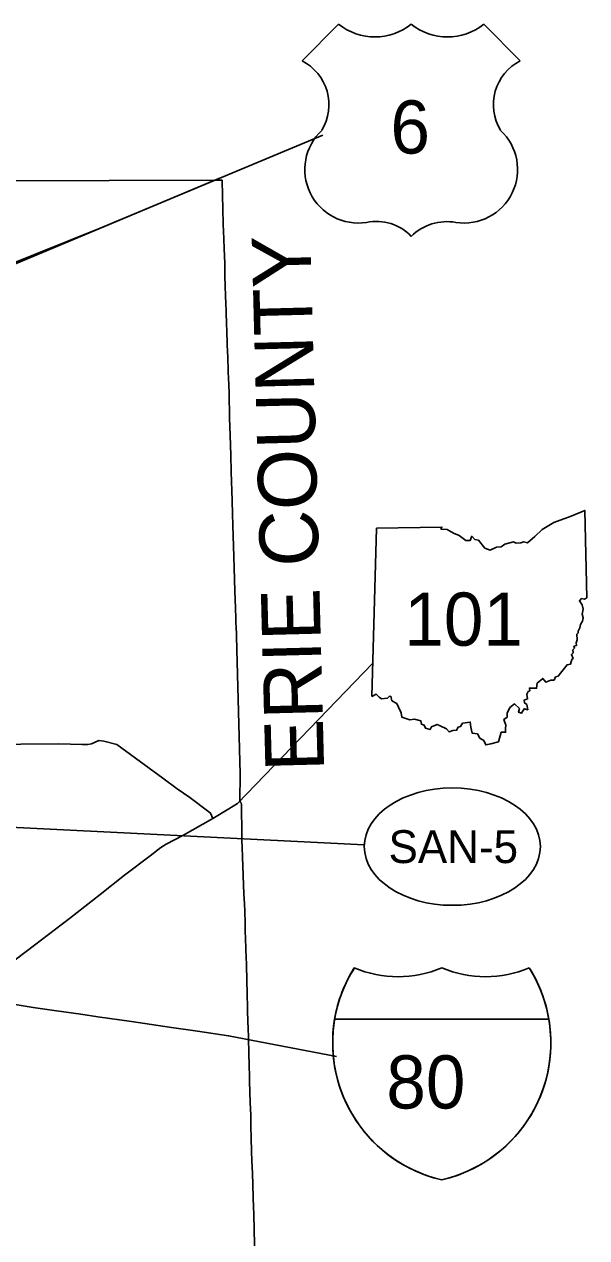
# Model space of a CAD drawing. Extents: x 0 to 798, y 0 to 440.
# Drawn here: x 540.4 to 588.3, y 195.7 to 299.1 of the extents above; entities that cross this region are included whole.
import ezdxf

# ---------------------------------------------------------------- set-up
doc = ezdxf.new("R2010")
doc.units = 0
for name, color, linetype in [('GM_X_Adjacent_County_Text', 7, 'Continuous'), ('GM_X_County', 7, 'Continuous'), ('GM_X_Interstate_Route', 7, 'Continuous'), ('GM_X_State_Route', 7, 'Continuous'), ('GM_X_US_Route', 7, 'Continuous'), ('PV_P_Text', 7, 'Continuous'), ('SH_Data', 7, 'Continuous'), ('SH_Text', 7, 'Continuous')]:
    doc.layers.add(name, color=color, linetype=linetype)

msp = doc.modelspace()

# ---------------------------------------------------------------- linework, layer by layer
at = {"layer": 'GM_X_County'}
msp.add_lwpolyline([(538.64, 285.73), (556.57, 285.78), (557.22, 285.79), (557.25, 284.49), (557.28, 283.34), (557.32, 282.03), (557.35, 280.8), (557.39, 279.94), (557.44, 278.71), (557.46, 277.81), (557.49, 276.58), (557.5, 276.13), (557.54, 275.1), (557.55, 274.86), (557.56, 274.65), (557.57, 274.17), (557.58, 273.91), (557.6, 273.34), (557.61, 273.13), (557.63, 272.64), (557.65, 272.15), (557.66, 271.82), (557.67, 271.13), (557.69, 270.77), (557.71, 270.33), (557.72, 269.89), (557.74, 269.4), (557.76, 268.95), (557.79, 268.34), (557.81, 267.68), (557.82, 267.02), (557.84, 266.16), (557.85, 265.69), (557.85, 265.67), (557.85, 265.53), (557.9, 264.03), (557.95, 262.35), (557.99, 260.95), (558.07, 258.49), (558.09, 257.35), (558.1, 257.18), (558.1, 257.1), (558.12, 256.65), (558.13, 256.36), (558.21, 253.74), (558.24, 252.76), (558.3, 250.79), (558.35, 249.36), (558.38, 248.45), (558.39, 248.08), (558.42, 247.68), (558.42, 247.55), (558.43, 247.27), (558.45, 246.57), (558.45, 246.41), (558.46, 246.37), (558.46, 246.25), (558.46, 246.15), (558.46, 246.03), (558.47, 245.95), (558.47, 245.8), (558.74, 235.2), (558.72, 232.88), (558.78, 232.8), (558.83, 232.73), (558.85, 232.69), (558.86, 232.65), (558.87, 232.64), (558.87, 232.62), (558.88, 232.58), (558.88, 232.33), (558.88, 232.29), (558.88, 232.17), (558.88, 232.09), (558.88, 231.68), (558.89, 230.9), (558.9, 229.46), (558.91, 229.01), (558.95, 228.07), (558.98, 227.41), (559.01, 226.51), (559.08, 224.99), (559.12, 224.14), (559.14, 223.51), (559.18, 222.49), (559.19, 221.87), (559.24, 220.4), (559.27, 219.43), (559.28, 219.13), (559.32, 217.4), (559.34, 216.71), (559.38, 215.06), (559.41, 214.12), (559.43, 213.51), (559.44, 213.27), (559.45, 213.02), (559.46, 212.75), (559.46, 212.58), (559.49, 211.5), (559.53, 210.27), (559.54, 209.53), (559.56, 209), (559.61, 207.2), (559.65, 206.14), (559.66, 205.68), (559.67, 205.11), (559.68, 204.27), (559.68, 204.24), (559.72, 203.01), (559.75, 202.28), (559.79, 201.17), (559.83, 200.23), (559.87, 199.12), (559.9, 198.3), (559.91, 197.73), (559.96, 196.33), (560, 194.03)], dxfattribs=at)
at = {"layer": 'GM_X_Interstate_Route'}
msp.add_lwpolyline([(535.41, 216.44), (535.96, 216.3), (536.34, 216.19), (538.05, 215.82), (541.14, 215.31), (543.1, 215.03), (545.19, 214.73), (546.63, 214.51), (549.5, 214.1), (552.9, 213.6), (555.12, 213.28), (557.77, 212.9), (566.97, 211.14)], dxfattribs=at)
at = {"layer": 'GM_X_State_Route'}
for points in [[(556.43, 231.42), (557.78, 232.23), (558.53, 232.68), (570.04, 244.63)], [(527.85, 237.12), (528.3, 237.17), (530.97, 237.53), (531.94, 237.65), (536.64, 237.68), (540.09, 237.73), (543.32, 237.76), (545.31, 237.72), (545.78, 237.71), (546.1, 237.77), (546.71, 238.04), (547.14, 237.99), (548.24, 237.71), (552.16, 234.85), (553.38, 233.93), (554.47, 233.19), (556.09, 231.97), (556.24, 231.87), (556.43, 231.42)], [(535.41, 216.44), (536.35, 217.09), (538.15, 218.33), (539.71, 219.45), (541.25, 220.63), (544.23, 222.9), (546.83, 224.93), (548.89, 226.57), (551.09, 228.23), (552.01, 228.93), (552.45, 229.22), (553.86, 229.97), (556.43, 231.42)]]:
    msp.add_lwpolyline(points, dxfattribs=at)
at = {"layer": 'GM_X_US_Route'}
msp.add_lwpolyline([(516.74, 268.96), (516.74, 268.97), (520.28, 270.51), (523.66, 272), (525.17, 272.65), (527.51, 273.65), (530.16, 274.76), (533.37, 276.17), (536.78, 277.61), (538.43, 278.33), (546.84, 281.71), (565.78, 289.63)], dxfattribs=at)
at = {"layer": 'PV_P_Text'}
for p, q in [((567.14, 299.07), (564.03, 295.96)), ((567.14, 299.07), (564.03, 295.96)), ((582.61, 295.96), (579.5, 299.07)), ((582.61, 295.96), (579.5, 299.07)), ((569.96, 241.79), (570.36, 256.15)), ((569.96, 241.79), (570.36, 256.15)), ((566.8, 214.31), (585.04, 214.31)), ((585.04, 214.31), (566.8, 214.31)), ((585.04, 214.31), (566.8, 214.31))]:
    msp.add_line(p, q, dxfattribs=at)
for points in [[(570.36, 256.15), (575.94, 256.24), (575.85, 256.07), (576.38, 256.03), (576.93, 255.73), (577.41, 255.53), (577.98, 255.08), (578.33, 255.08), (578.48, 255.46), (578.74, 255.17), (579.06, 255.12), (579.6, 254.43), (580.05, 254.28), (580.58, 254.52), (580.99, 254.55), (581.28, 254.79), (582.04, 254.99), (582.26, 254.87), (582.66, 254.89), (582.87, 254.98), (583.22, 254.9), (583.84, 255.42), (584.48, 256.04), (585.46, 256.62), (586.93, 257.17), (588.1, 257.66), (588.27, 250.21)], [(570.36, 256.15), (575.94, 256.24), (575.85, 256.07), (576.38, 256.03), (576.93, 255.73), (577.41, 255.53), (577.98, 255.08), (578.33, 255.08), (578.48, 255.46), (578.74, 255.17), (579.06, 255.12), (579.6, 254.43), (580.05, 254.28), (580.58, 254.52), (580.99, 254.55), (581.28, 254.79), (582.04, 254.99), (582.26, 254.87), (582.66, 254.89), (582.87, 254.98), (583.22, 254.9), (583.84, 255.42), (584.48, 256.04), (585.46, 256.62), (586.93, 257.17), (588.1, 257.66), (588.27, 250.21)], [(588.27, 250.21), (588.09, 250.1), (587.83, 250.15), (587.65, 249.94), (587.87, 249.6), (587.97, 249.23), (587.88, 248.82), (587.97, 248.49), (587.91, 248.21), (587.74, 247.93), (587.68, 247.66), (587.54, 247.38), (587.55, 247.22), (587.42, 247.1), (587.44, 246.63), (587.37, 246.37), (587.4, 246.15), (587.18, 246.09), (587.23, 245.91), (587.09, 245.77), (587.12, 245.52), (586.96, 245.37), (587.11, 245.05), (586.99, 244.95), (586.89, 244.57), (586.6, 244.5), (586.04, 243.8), (585.84, 243.54), (585.61, 243.47), (585.49, 243.2), (585.21, 243.2), (584.79, 243.01), (584.52, 243.34), (584.05, 242.95), (583.99, 242.5), (583.39, 242.52), (583.42, 242.29), (583.28, 242.22), (583.16, 242), (583.23, 241.59), (582.95, 241.49), (582.98, 241.26), (583.16, 241.11), (583.24, 240.67), (582.95, 240.76), (582.7, 240.38), (582.45, 240.47), (582.53, 240.79), (582.11, 241.17), (581.71, 240.86), (581.5, 240.37), (581.49, 240.04), (581.2, 239.84), (581.39, 239.37), (581.35, 239.05), (581.36, 238.75), (580.98, 238.76), (580.76, 237.93)], [(588.27, 250.21), (588.09, 250.1), (587.83, 250.15), (587.65, 249.94), (587.87, 249.6), (587.97, 249.23), (587.88, 248.82), (587.97, 248.49), (587.91, 248.21), (587.74, 247.93), (587.68, 247.66), (587.54, 247.38), (587.55, 247.22), (587.42, 247.1), (587.44, 246.63), (587.37, 246.37), (587.4, 246.15), (587.18, 246.09), (587.23, 245.91), (587.09, 245.77), (587.12, 245.52), (586.96, 245.37), (587.11, 245.05), (586.99, 244.95), (586.89, 244.57), (586.6, 244.5), (586.04, 243.8), (585.84, 243.54), (585.61, 243.47), (585.49, 243.2), (585.21, 243.2), (584.79, 243.01), (584.52, 243.34), (584.05, 242.95), (583.99, 242.5), (583.39, 242.52), (583.42, 242.29), (583.28, 242.22), (583.16, 242), (583.23, 241.59), (582.95, 241.49), (582.98, 241.26), (583.16, 241.11), (583.24, 240.67), (582.95, 240.76), (582.7, 240.38), (582.45, 240.47), (582.53, 240.79), (582.11, 241.17), (581.71, 240.86), (581.5, 240.37), (581.49, 240.04), (581.2, 239.84), (581.39, 239.37), (581.35, 239.05), (581.36, 238.75), (580.98, 238.76), (580.76, 237.93)], [(580.76, 237.93), (580.11, 237.78), (579.66, 237.68), (579.5, 238.06), (579.17, 238.25), (578.96, 238.63), (578.5, 238.68), (578.39, 239.2), (578.34, 239.62), (577.7, 239.52), (577.53, 239.26), (577.31, 239.19), (577.18, 238.93), (576.87, 238.91), (576.54, 238.79), (576.32, 239.04), (575.79, 239.3), (575.54, 239.43), (575.04, 239.22), (574.93, 238.98), (574.53, 239.09), (574.43, 239.36), (574.19, 239.44), (574.13, 239.73), (573.61, 239.88), (573.21, 239.82), (572.51, 240.05), (572.47, 240.42), (572.23, 240.88), (572.1, 241.2), (571.66, 241.44), (571.57, 241.82), (571.43, 241.81), (571.3, 241.66), (570.8, 241.59), (570.6, 241.74), (570.33, 242.01), (569.96, 241.79)], [(580.76, 237.93), (580.11, 237.78), (579.66, 237.68), (579.5, 238.06), (579.17, 238.25), (578.96, 238.63), (578.5, 238.68), (578.39, 239.2), (578.34, 239.62), (577.7, 239.52), (577.53, 239.26), (577.31, 239.19), (577.18, 238.93), (576.87, 238.91), (576.54, 238.79), (576.32, 239.04), (575.79, 239.3), (575.54, 239.43), (575.04, 239.22), (574.93, 238.98), (574.53, 239.09), (574.43, 239.36), (574.19, 239.44), (574.13, 239.73), (573.61, 239.88), (573.21, 239.82), (572.51, 240.05), (572.47, 240.42), (572.23, 240.88), (572.1, 241.2), (571.66, 241.44), (571.57, 241.82), (571.43, 241.81), (571.3, 241.66), (570.8, 241.59), (570.6, 241.74), (570.33, 242.01), (569.96, 241.79)]]:
    msp.add_lwpolyline(points, dxfattribs=at)
for centre, radius, start, end in [((570.23, 303), 5, 231.813, 308.187), ((570.23, 303), 5, 231.813, 308.187), ((576.41, 303), 5, 231.813, 308.187), ((576.41, 303), 5, 231.813, 308.187), ((562.08, 292.21), 4.23, 329.1175, 62.6108), ((562.08, 292.21), 4.23, 329.1175, 62.6108), ((584.55, 292.21), 4.23, 117.3892, 210.8825), ((584.55, 292.21), 4.23, 117.3892, 210.8825), ((568.82, 286.7), 4.56, 133.0046, 278.7282), ((568.82, 286.7), 4.56, 133.0046, 278.7282), ((577.82, 286.7), 4.56, 261.2718, 46.9954), ((577.82, 286.7), 4.56, 261.2718, 46.9954), ((570.36, 278.2), 4.08, 43.4177, 101.8742), ((570.36, 278.2), 4.08, 43.4177, 101.8742), ((576.37, 277.93), 4.33, 79.9613, 134.7468), ((576.37, 277.93), 4.33, 79.9613, 134.7468), ((578.62, 212.3), 11.99, 147.8216, 256.9941), ((577.87, 212.51), 11.22, 146.654, 170.759), ((572.2, 227.5), 9.57, 247.0848, 292.9105), ((572.2, 227.5), 9.57, 247.0848, 292.9105), ((573.22, 212.3), 11.99, 283.0065, 32.1787), ((579.65, 227.5), 9.57, 247.0916, 292.9084), ((579.65, 227.5), 9.57, 247.0916, 292.9084), ((573.22, 212.3), 11.99, 9.6475, 32.179), ((578.62, 212.3), 11.99, 170.3514, 256.9967), ((573.25, 212.3), 11.97, 282.7667, 9.6898)]:
    msp.add_arc(centre, radius, start, end, dxfattribs=at)
at = {"layer": 'SH_Data'}
msp.add_line((569.32, 229.17), (493.27, 232.95), dxfattribs=at)
msp.add_ellipse((576.82, 229.01), major_axis=(7.5, 0), ratio=0.666667, dxfattribs=at)
at = {"layer": 'SH_Text'}
msp.add_lwpolyline([(446.9, 256.63), (452.1, 259.59), (456.65, 261.66), (462.56, 264.3), (465.11, 265.36), (467.91, 265.97), (471.47, 266.06), (481.46, 266.37), (485, 266.46), (491.84, 266.01), (497.56, 265.67), (504.32, 265.72), (508.68, 265.69), (510.64, 266.24), (523.8, 272.05), (556.95, 285.94)], dxfattribs=at)

# ---------------------------------------------------------------- texts
at = {"layer": 'GM_X_Adjacent_County_Text'}
msp.add_text('ERIE COUNTY', height=5, rotation=91.4817, dxfattribs=at).set_placement((565.91, 235.47))
at = {"layer": 'PV_P_Text'}
for s, height, p in [('6', 4.53, (571.55, 288.06)), ('101', 4.528, (572.73, 246.13)), ('80', 4.528, (571.2, 206.7))]:
    msp.add_text(s, height=height, dxfattribs=at).set_placement(p)
at = {"layer": 'SH_Data'}
msp.add_text('SAN-5', height=2.8, dxfattribs=at).set_placement((571.39, 227.61))

doc.saveas('drawing.dxf')
